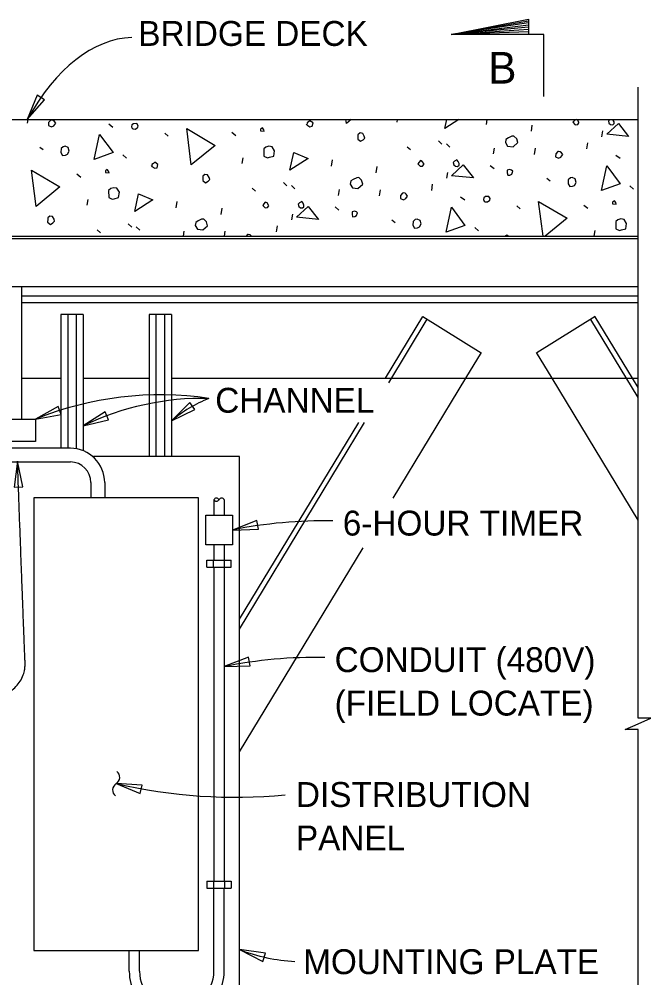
# Model space of a CAD drawing. Extents: x 927736.2 to 927809.6, y 636703.6 to 636757.7.
# Drawn here: x 927764.73 to 927774.19, y 636743.33 to 636757.7 of the extents above; entities that cross this region are included whole.
import ezdxf

# ---------------------------------------------------------------- set-up
doc = ezdxf.new("R2010")
doc.units = 0
for name, color, linetype in [('DimLines_dp', 7, 'Continuous'), ('Miscellaneous1', 7, 'Continuous'), ('Miscellaneous2', 7, 'Continuous'), ('Miscellaneous3', 7, 'Continuous')]:
    doc.layers.add(name, color=color, linetype=linetype)

msp = doc.modelspace()

# ---------------------------------------------------------------- linework, layer by layer
at = {"layer": 'DimLines_dp'}
for p, q in [((927771.201, 636757.464), (927772.357, 636757.668)), ((927772.357, 636757.643), (927771.201, 636757.464)), ((927771.201, 636757.464), (927772.357, 636757.612)), ((927772.357, 636757.578), (927771.201, 636757.464)), ((927771.201, 636757.464), (927772.357, 636757.544)), ((927772.357, 636757.507), (927771.201, 636757.464))]:
    msp.add_line(p, q, dxfattribs=at)
for points in [[(927772.589, 636756.539), (927772.589, 636757.464), (927771.201, 636757.464), (927772.357, 636757.695), (927772.357, 636757.464)], [(927774, 636737.782), (927774, 636747.055), (927773.809, 636747.055), (927774, 636747.139), (927774.191, 636747.222), (927774, 636747.222), (927774, 636756.677)]]:
    msp.add_lwpolyline(points, dxfattribs=at)
for points in [[(927764.852, 636756.193), (927765.11, 636756.486), (927764.999, 636756.555)], [(927764.974, 636751.702), (927765.359, 636751.771), (927765.315, 636751.894)], [(927767.01, 636751.678), (927767.362, 636751.848), (927767.286, 636751.954)], [(927765.688, 636751.603), (927766.068, 636751.693), (927766.018, 636751.813)], [(927764.705, 636751.071), (927764.654, 636750.684), (927764.785, 636750.688)], [(927767.924, 636750.042), (927768.314, 636750.055), (927768.288, 636750.183)], [(927767.801, 636747.996), (927768.191, 636748.009), (927768.165, 636748.137)], [(927766.183, 636746.244), (927766.543, 636746.093), (927766.573, 636746.221)], [(927768.032, 636743.756), (927768.38, 636743.579), (927768.419, 636743.703)]]:
    msp.add_lwpolyline(points, close=True, dxfattribs=at)
for centre, radius, start, end in [((927766.848, 636747.067), 5, 81.6635, 112.0069), ((927767.492, 636747.853), 4.162, 88.8828, 115.6789), ((927768.324, 636750.113), 2.043, 111.5678, 130.0212), ((927769.285, 636743.338), 6.841, 88.7814, 101.4782), ((927769.162, 636741.292), 6.841, 88.7814, 101.4782), ((927766.126, 636746.337), 0.11, 301.142, 52.8692), ((927766.24, 636746.148), 0.11, 121.142, 232.8692), ((927767.974, 636753.978), 7.939, 256.9627, 275.3449), ((927768.996, 636746.243), 2.667, 248.8193, 267.0903)]:
    msp.add_arc(centre, radius, start, end, dxfattribs=at)
msp.add_ellipse((927766.69, 636751.583), major_axis=(0.274, -5.84), ratio=0.464296, start_param=3.141604, end_param=3.781059, dxfattribs=at)
msp.add_open_spline([(927758.883, 636747.305), (927762.516, 636747.33), (927764.844, 636747.456), (927764.793, 636748.678), (927764.705, 636751.071)], degree=2, dxfattribs=at)
at = {"layer": 'Miscellaneous1'}
for p, q in [((927765.354, 636753.27), (927765.354, 636751.267)), ((927765.688, 636753.27), (927765.354, 636753.27)), ((927765.457, 636753.27), (927765.457, 636751.267)), ((927765.586, 636753.27), (927765.586, 636751.259)), ((927765.688, 636753.27), (927765.688, 636751.23)), ((927767.01, 636753.27), (927766.676, 636753.27)), ((927766.676, 636753.27), (927766.676, 636751.141)), ((927766.778, 636753.27), (927766.778, 636751.141)), ((927766.907, 636753.27), (927766.907, 636751.141)), ((927767.01, 636753.27), (927767.01, 636751.141)), ((927763.253, 636751.702), (927764.974, 636751.702)), ((927764.974, 636751.702), (927764.974, 636751.368)), ((927764.974, 636751.368), (927764.014, 636751.368)), ((927765.497, 636751.267), (927764.242, 636751.267)), ((927764.242, 636751.062), (927765.497, 636751.061)), ((927765.805, 636750.753), (927765.805, 636750.524)), ((927766.011, 636750.753), (927766.011, 636750.524)), ((927767.646, 636750.497), (927767.646, 636750.262)), ((927767.801, 636750.497), (927767.801, 636750.262)), ((927767.646, 636749.822), (927767.646, 636749.588)), ((927767.801, 636749.822), (927767.801, 636749.588)), ((927767.646, 636749.485), (927767.646, 636744.78)), ((927767.801, 636749.485), (927767.801, 636744.78)), ((927767.646, 636743.432), (927767.646, 636744.677)), ((927767.801, 636743.432), (927767.801, 636744.677)), ((927766.379, 636743.432), (927766.379, 636743.741)), ((927766.533, 636743.432), (927766.533, 636743.741))]:
    msp.add_line(p, q, dxfattribs=at)
for points in [[(927767.415, 636750.524), (927764.949, 636750.524), (927764.949, 636743.741), (927767.415, 636743.741)], [(927767.524, 636750.262), (927767.924, 636750.262), (927767.924, 636749.822), (927767.524, 636749.822)]]:
    msp.add_lwpolyline(points, close=True, dxfattribs=at)
for centre, radius, start, end in [((927765.497, 636750.753), 0.514, 0, 89.9792), ((927765.497, 636750.753), 0.308, 0, 89.9792), ((927767.685, 636750.475), 0.0441, 29.0027, 150.9974), ((927767.685, 636750.518), 0.0441, 209.003, 330.9971), ((927767.762, 636750.475), 0.0441, 29.0028, 150.9973), ((927767.09, 636743.432), 0.711, 179.9955, 0.0001), ((927767.09, 636743.432), 0.557, 180, 0)]:
    msp.add_arc(centre, radius, start, end, dxfattribs=at)
at = {"layer": 'Miscellaneous2'}
for p, q in [((927753.063, 636756.193), (927774, 636756.193)), ((927764.855, 636756.138), (927764.863, 636756.193)), ((927770.393, 636756.153), (927770.399, 636756.193)), ((927771.731, 636756.116), (927771.742, 636756.193)), ((927766.072, 636756.125), (927766.135, 636756.079)), ((927767.918, 636756.001), (927767.976, 636755.953)), ((927772.402, 636756.015), (927772.416, 636756.108)), ((927773.458, 636755.934), (927773.473, 636756.021)), ((927766.913, 636755.987), (927766.963, 636755.943)), ((927771.011, 636755.872), (927771.062, 636755.822)), ((927765.041, 636755.779), (927765.089, 636755.741)), ((927770.542, 636755.785), (927770.593, 636755.741)), ((927771.131, 636755.828), (927771.183, 636755.778)), ((927771.835, 636755.678), (927771.85, 636755.765)), ((927772.45, 636755.67), (927772.463, 636755.763)), ((927773.232, 636755.752), (927773.246, 636755.845)), ((927766.284, 636755.665), (927766.336, 636755.615)), ((927768.07, 636755.531), (927768.085, 636755.618)), ((927769.407, 636755.493), (927769.421, 636755.586)), ((927773.666, 636755.658), (927773.73, 636755.611)), ((927770.079, 636755.393), (927770.093, 636755.486)), ((927771.786, 636755.505), (927771.843, 636755.457)), ((927765.595, 636755.378), (927765.653, 636755.33)), ((927771.135, 636755.312), (927771.15, 636755.399)), ((927772.636, 636755.311), (927772.684, 636755.273)), ((927768.219, 636755.162), (927768.269, 636755.118)), ((927768.688, 636755.249), (927768.739, 636755.2)), ((927768.808, 636755.205), (927768.86, 636755.155)), ((927769.512, 636755.055), (927769.527, 636755.142)), ((927770.127, 636755.048), (927770.14, 636755.141)), ((927770.909, 636755.13), (927770.923, 636755.223)), ((927773.879, 636755.198), (927773.931, 636755.148)), ((927765.747, 636754.908), (927765.762, 636754.995)), ((927771.343, 636755.035), (927771.407, 636754.989)), ((927767.084, 636754.871), (927767.098, 636754.964)), ((927767.756, 636754.77), (927767.77, 636754.863)), ((927769.463, 636754.883), (927769.52, 636754.834)), ((927772.185, 636754.897), (927772.235, 636754.853)), ((927773.19, 636754.911), (927773.247, 636754.862)), ((927768.812, 636754.689), (927768.827, 636754.776)), ((927766.365, 636754.627), (927766.416, 636754.577)), ((927766.485, 636754.583), (927766.537, 636754.533)), ((927768.586, 636754.507), (927768.6, 636754.6)), ((927770.313, 636754.689), (927770.361, 636754.651)), ((927771.556, 636754.575), (927771.608, 636754.525)), ((927762.11, 636754.446), (927774, 636754.446)), ((927765.896, 636754.54), (927765.946, 636754.496)), ((927767.191, 636754.446), (927767.204, 636754.52)), ((927767.807, 636754.446), (927767.817, 636754.518)), ((927773.342, 636754.446), (927773.356, 636754.528)), ((927762.121, 636754.407), (927774, 636754.407)), ((927760.453, 636753.688), (927774, 636753.688))]:
    msp.add_line(p, q, dxfattribs=at)
for points in [[(927765.172, 636756.146), (927765.171, 636756.101), (927765.215, 636756.081), (927765.249, 636756.097), (927765.277, 636756.136), (927765.257, 636756.163), (927765.241, 636756.177), (927765.213, 636756.183), (927765.202, 636756.18), (927765.172, 636756.146)], [(927769.038, 636756.11), (927769.083, 636756.083), (927769.119, 636756.093), (927769.132, 636756.141), (927769.085, 636756.173), (927769.064, 636756.155), (927769.042, 636756.142), (927769.038, 636756.11), (927769.035, 636756.121)], [(927769.632, 636756.134), (927769.624, 636756.193)], [(927769.702, 636756.193), (927769.632, 636756.134)], [(927771.108, 636756.058), (927771.137, 636756.193)], [(927771.318, 636756.193), (927771.108, 636756.058)], [(927773.024, 636756.15), (927773.059, 636756.114), (927773.096, 636756.118), (927773.115, 636756.142), (927773.112, 636756.154), (927773.091, 636756.187), (927773.075, 636756.193)], [(927773.058, 636756.193), (927773.043, 636756.174), (927773.024, 636756.15)], [(927773.581, 636756.193), (927773.575, 636756.189), (927773.555, 636756.171), (927773.564, 636756.135)], [(927773.564, 636756.135), (927773.588, 636756.116), (927773.621, 636756.112), (927773.642, 636756.13), (927773.642, 636756.156), (927773.628, 636756.184), (927773.621, 636756.193)], [(927766.421, 636756.06), (927766.436, 636756.051), (927766.475, 636756.048), (927766.506, 636756.076), (927766.513, 636756.097), (927766.492, 636756.13), (927766.441, 636756.129), (927766.42, 636756.11), (927766.415, 636756.083), (927766.421, 636756.06)], [(927767.308, 636755.512), (927767.24, 636756.055), (927767.664, 636755.805), (927767.308, 636755.512)], [(927768.347, 636756.02), (927768.399, 636756.015), (927768.393, 636756.039), (927768.373, 636756.065), (927768.347, 636756.046), (927768.347, 636756.02)], [(927773.531, 636755.973), (927773.705, 636756.134), (927773.859, 636755.939), (927773.531, 636755.973)], [(927765.856, 636755.595), (927765.935, 636755.968), (927766.136, 636755.696), (927765.856, 636755.595)], [(927769.804, 636755.944), (927769.803, 636755.9), (927769.844, 636755.866), (927769.882, 636755.889), (927769.907, 636755.915), (927769.9, 636755.945), (927769.876, 636755.983), (927769.836, 636755.991), (927769.805, 636755.964), (927769.804, 636755.944)], [(927772.013, 636755.847), (927772.047, 636755.792), (927772.127, 636755.782), (927772.199, 636755.846), (927772.183, 636755.905), (927772.14, 636755.945), (927772.109, 636755.943), (927772.058, 636755.917), (927772.02, 636755.893), (927772.013, 636755.847)], [(927765.36, 636755.756), (927765.356, 636755.698), (927765.381, 636755.653), (927765.424, 636755.658), (927765.452, 636755.672), (927765.479, 636755.718), (927765.464, 636755.771), (927765.421, 636755.791), (927765.391, 636755.783), (927765.36, 636755.756)], [(927768.393, 636755.752), (927768.397, 636755.644), (927768.448, 636755.619), (927768.478, 636755.627), (927768.543, 636755.645), (927768.554, 636755.724), (927768.519, 636755.785), (927768.472, 636755.792), (927768.424, 636755.779), (927768.393, 636755.752)], [(927772.767, 636755.679), (927772.766, 636755.634), (927772.81, 636755.614), (927772.844, 636755.629), (927772.872, 636755.668), (927772.852, 636755.695), (927772.835, 636755.71), (927772.808, 636755.715), (927772.796, 636755.712), (927772.767, 636755.679)], [(927768.785, 636755.435), (927768.842, 636755.699), (927769.057, 636755.61), (927768.785, 636755.435)], [(927770.701, 636755.527), (927770.736, 636755.492), (927770.773, 636755.495), (927770.792, 636755.52), (927770.789, 636755.532), (927770.768, 636755.564), (927770.739, 636755.576), (927770.72, 636755.551), (927770.701, 636755.527)], [(927771.241, 636755.512), (927771.265, 636755.493), (927771.298, 636755.489), (927771.319, 636755.508), (927771.319, 636755.533), (927771.305, 636755.561), (927771.285, 636755.588), (927771.252, 636755.566), (927771.231, 636755.548), (927771.241, 636755.512)], [(927764.985, 636754.89), (927764.916, 636755.433), (927765.341, 636755.183), (927764.985, 636754.89)], [(927766.024, 636755.398), (927766.076, 636755.393), (927766.07, 636755.416), (927766.05, 636755.443), (927766.024, 636755.423), (927766.024, 636755.398)], [(927766.715, 636755.487), (927766.76, 636755.461), (927766.796, 636755.47), (927766.809, 636755.519), (927766.762, 636755.551), (927766.741, 636755.532), (927766.719, 636755.52), (927766.715, 636755.487), (927766.712, 636755.499)], [(927771.208, 636755.35), (927771.382, 636755.512), (927771.536, 636755.317), (927771.208, 636755.35)], [(927772.039, 636755.394), (927772.048, 636755.358), (927772.08, 636755.36), (927772.108, 636755.374), (927772.122, 636755.416), (927772.106, 636755.431), (927772.077, 636755.443), (927772.041, 636755.433), (927772.039, 636755.394)], [(927773.451, 636755.128), (927773.53, 636755.5), (927773.73, 636755.228), (927773.451, 636755.128)], [(927767.481, 636755.322), (927767.48, 636755.277), (927767.521, 636755.243), (927767.559, 636755.266), (927767.584, 636755.292), (927767.576, 636755.322), (927767.553, 636755.361), (927767.513, 636755.369), (927767.482, 636755.341), (927767.481, 636755.322)], [(927769.69, 636755.224), (927769.724, 636755.17), (927769.804, 636755.159), (927769.876, 636755.223), (927769.86, 636755.283), (927769.817, 636755.322), (927769.786, 636755.32), (927769.735, 636755.294), (927769.697, 636755.271), (927769.69, 636755.224)], [(927772.955, 636755.288), (927772.951, 636755.23), (927772.976, 636755.186), (927773.019, 636755.191), (927773.047, 636755.205), (927773.073, 636755.25), (927773.059, 636755.304), (927773.015, 636755.324), (927772.986, 636755.316), (927772.955, 636755.288)], [(927766.07, 636755.129), (927766.074, 636755.022), (927766.125, 636754.997), (927766.155, 636755.005), (927766.22, 636755.022), (927766.231, 636755.102), (927766.195, 636755.163), (927766.149, 636755.169), (927766.101, 636755.157), (927766.07, 636755.129)], [(927766.462, 636754.813), (927766.519, 636755.077), (927766.734, 636754.988), (927766.462, 636754.813)], [(927770.444, 636755.056), (927770.443, 636755.011), (927770.487, 636754.991), (927770.521, 636755.007), (927770.549, 636755.046), (927770.529, 636755.073), (927770.512, 636755.087), (927770.485, 636755.093), (927770.473, 636755.09), (927770.444, 636755.056)], [(927771.693, 636754.969), (927771.708, 636754.961), (927771.747, 636754.958), (927771.778, 636754.986), (927771.785, 636755.007), (927771.764, 636755.039), (927771.713, 636755.039), (927771.692, 636755.02), (927771.687, 636754.993), (927771.693, 636754.969)], [(927768.378, 636754.905), (927768.413, 636754.869), (927768.45, 636754.873), (927768.469, 636754.897), (927768.466, 636754.909), (927768.444, 636754.942), (927768.416, 636754.953), (927768.397, 636754.929), (927768.378, 636754.905)], [(927768.885, 636754.728), (927769.059, 636754.889), (927769.213, 636754.694), (927768.885, 636754.728)], [(927768.918, 636754.89), (927768.942, 636754.871), (927768.975, 636754.867), (927768.996, 636754.885), (927768.995, 636754.911), (927768.982, 636754.939), (927768.962, 636754.965), (927768.929, 636754.944), (927768.908, 636754.926), (927768.918, 636754.89)], [(927771.128, 636754.505), (927771.207, 636754.878), (927771.407, 636754.606), (927771.128, 636754.505)], [(927772.577, 636754.446), (927772.511, 636754.965), (927772.936, 636754.715), (927772.609, 636754.446)], [(927773.619, 636754.93), (927773.671, 636754.925), (927773.665, 636754.949), (927773.645, 636754.975), (927773.618, 636754.955), (927773.619, 636754.93)], [(927765.158, 636754.699), (927765.157, 636754.655), (927765.198, 636754.621), (927765.236, 636754.644), (927765.261, 636754.67), (927765.253, 636754.7), (927765.23, 636754.738), (927765.19, 636754.746), (927765.159, 636754.719), (927765.158, 636754.699)], [(927769.716, 636754.772), (927769.725, 636754.736), (927769.757, 636754.738), (927769.785, 636754.752), (927769.799, 636754.794), (927769.782, 636754.809), (927769.754, 636754.82), (927769.718, 636754.811), (927769.716, 636754.772)], [(927767.367, 636754.602), (927767.401, 636754.547), (927767.48, 636754.537), (927767.553, 636754.601), (927767.537, 636754.66), (927767.494, 636754.7), (927767.463, 636754.698), (927767.412, 636754.672), (927767.374, 636754.648), (927767.367, 636754.602)], [(927770.632, 636754.666), (927770.628, 636754.608), (927770.653, 636754.563), (927770.696, 636754.568), (927770.724, 636754.582), (927770.75, 636754.628), (927770.736, 636754.681), (927770.692, 636754.701), (927770.662, 636754.693), (927770.632, 636754.666)], [(927773.665, 636754.662), (927773.669, 636754.554), (927773.72, 636754.529), (927773.75, 636754.537), (927773.815, 636754.555), (927773.826, 636754.634), (927773.79, 636754.695), (927773.744, 636754.702), (927773.696, 636754.689), (927773.665, 636754.662)], [(927768.209, 636754.446), (927768.206, 636754.45), (927768.189, 636754.465), (927768.162, 636754.47), (927768.15, 636754.467), (927768.132, 636754.446)], [(927772.055, 636754.446), (927772.034, 636754.461), (927772.017, 636754.446)]]:
    msp.add_lwpolyline(points, dxfattribs=at)
at = {"layer": 'Miscellaneous3'}
for p, q in [((927764.769, 636751.702), (927764.769, 636753.688)), ((927764.769, 636753.552), (927774, 636753.552)), ((927764.769, 636753.449), (927774, 636753.449)), ((927770.219, 636752.319), (927770.777, 636753.242)), ((927770.266, 636752.248), (927770.843, 636753.201)), ((927770.777, 636753.242), (927771.65, 636752.699)), ((927773.356, 636753.242), (927772.483, 636752.699)), ((927774, 636752.029), (927773.294, 636753.197)), ((927773.915, 636752.319), (927773.36, 636753.237)), ((927771.42, 636752.319), (927771.654, 636752.704)), ((927772.713, 636752.319), (927772.48, 636752.704)), ((927764.769, 636752.319), (927765.354, 636752.319)), ((927765.688, 636752.319), (927766.676, 636752.319)), ((927767.01, 636752.319), (927774, 636752.319)), ((927770.332, 636750.519), (927771.42, 636752.319)), ((927774, 636750.191), (927772.713, 636752.319)), ((927774, 636752.178), (927773.915, 636752.319)), ((927768.032, 636748.704), (927769.816, 636751.653)), ((927768.032, 636748.555), (927769.905, 636751.652)), ((927768.032, 636746.717), (927769.883, 636749.777)), ((927767.543, 636749.588), (927767.904, 636749.588)), ((927767.543, 636749.485), (927767.543, 636749.588)), ((927767.64, 636749.485), (927767.64, 636749.588)), ((927767.807, 636749.485), (927767.807, 636749.588)), ((927767.904, 636749.485), (927767.904, 636749.588)), ((927767.543, 636749.485), (927767.904, 636749.485)), ((927767.543, 636744.78), (927767.904, 636744.78)), ((927767.543, 636744.78), (927767.543, 636744.677)), ((927767.543, 636744.677), (927767.904, 636744.677)), ((927767.64, 636744.78), (927767.64, 636744.677)), ((927767.807, 636744.78), (927767.807, 636744.677)), ((927767.904, 636744.78), (927767.904, 636744.677))]:
    msp.add_line(p, q, dxfattribs=at)
msp.add_lwpolyline([(927767.73, 636743.124), (927768.032, 636743.124), (927768.032, 636751.141), (927765.842, 636751.141)], dxfattribs=at)

# ---------------------------------------------------------------- texts
at = {"layer": 'DimLines_dp'}
for s, height, p in [('BRIDGE DECK', 0.37296, (927766.515, 636757.295)), ('B', 0.474, (927771.756, 636756.73)), ('CHANNEL', 0.373, (927767.667, 636751.799)), ('6-HOUR TIMER', 0.37296, (927769.578, 636749.959)), ('CONDUIT (480V)', 0.37296, (927769.455, 636747.913)), ('(FIELD LOCATE)', 0.37296, (927769.455, 636747.262)), ('DISTRIBUTION ', 0.37296, (927768.876, 636745.893)), ('PANEL', 0.373, (927768.876, 636745.242)), ('MOUNTING PLATE', 0.37296, (927768.984, 636743.388))]:
    msp.add_text(s, height=height, dxfattribs=at).set_placement(p)

doc.saveas('drawing.dxf')
